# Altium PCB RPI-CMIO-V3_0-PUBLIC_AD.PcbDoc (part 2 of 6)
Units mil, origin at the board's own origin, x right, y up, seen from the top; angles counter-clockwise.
Board outline 3295.4 x 4105.44 mil, 6 copper layers (TOP, GNDT, PWRT, PWRB, GNDB, BOTTOM); 114 components, 152 nets, 703 pads, 476 vias.
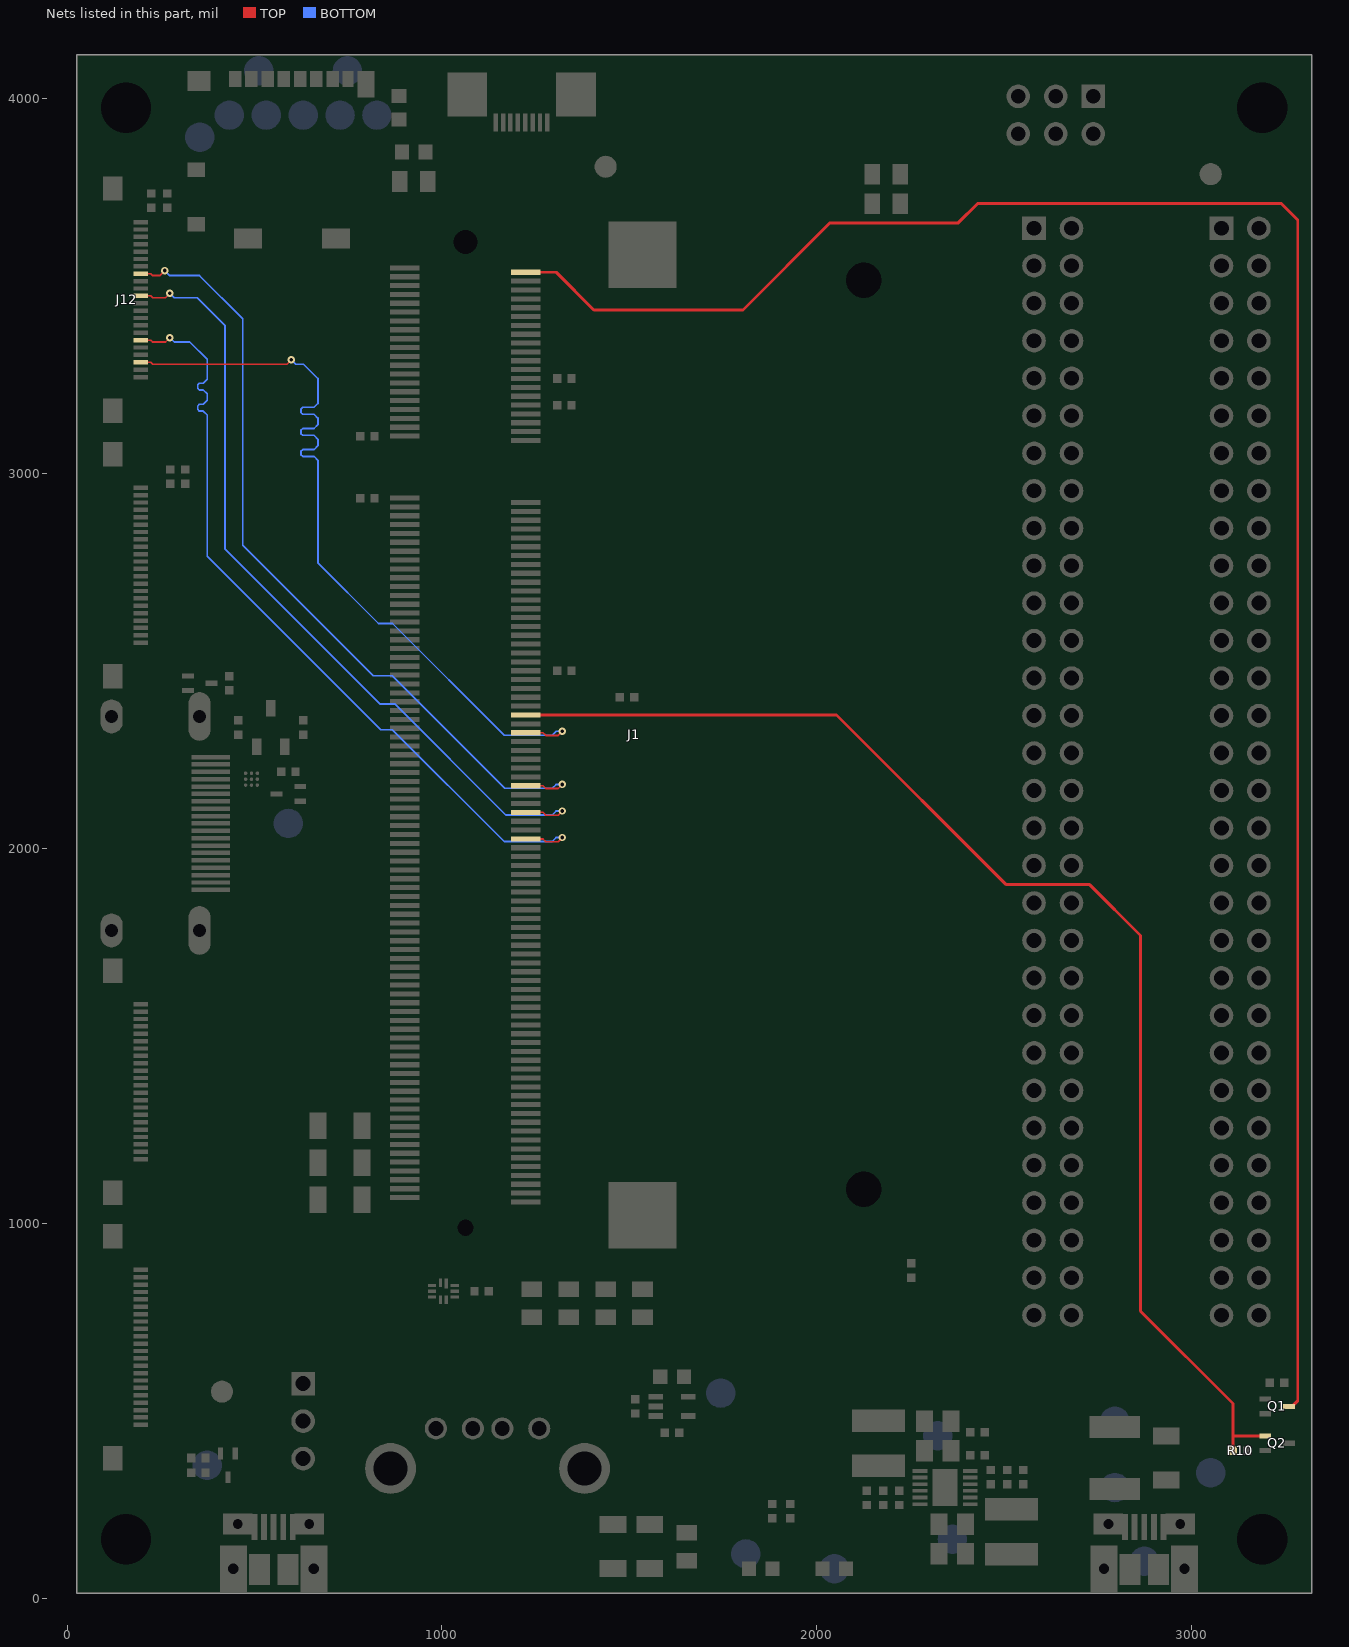
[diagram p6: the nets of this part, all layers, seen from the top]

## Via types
v1: diameter 19.68, hole 9.84, TOP to BOTTOM, 476 vias

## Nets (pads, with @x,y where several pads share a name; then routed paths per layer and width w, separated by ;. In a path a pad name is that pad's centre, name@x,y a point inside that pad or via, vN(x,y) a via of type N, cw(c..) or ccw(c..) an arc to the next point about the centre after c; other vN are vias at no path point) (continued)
DSI1_DP0: J1.94 J12.3 | length 2162.4
  TOP w4.53: J1.94@1224.41,2309.05 1269.72,2309.05 1277,2301.77 1310.25,2301.77 v1(1321.22,2312.74)
  TOP w4.57: J12.3@196.85,3297.24 223.39,3297.24 228.29,3292.34 586.81,3292.34 v1(598.42,3303.96)
  BOTTOM w4.57: v1(598.42,3303.96) 610.04,3292.35 631.08,3292.35 669.33,3254.09 669.33,3187.32 658.98,3176.96 628.62,3176.96 624.06,3172.39 624.06,3163.26 628.62,3158.69 658.98,3158.69 669.33,3148.34 669.33,3131.02 658.98,3120.66 628.62,3120.66 624.06,3116.09 624.06,3106.96 628.62,3102.39 658.98,3102.39 669.33,3092.04 669.33,3074.72 658.98,3064.36 628.62,3064.36 624.06,3059.8 624.06,3050.66 628.62,3046.1 658.98,3046.1 669.33,3035.74 669.33,2761.97 830.87,2600.43 868.27,2600.43 1166.52,2302.18 1294.23,2302.18 1304.79,2312.74 v1(1321.22,2312.74)
DSI1_DP1: J1.118 J12.6 | length 2171.9
  TOP w4.53: J1.118@1224.41,2025.59 1269.72,2025.59 1277,2018.31 1310.25,2018.31 v1(1321.22,2029.28)
  TOP w4.57: J12.6@196.85,3356.3 223.39,3356.3 228.29,3351.4 249,3351.4 262.7,3351.39 v1(274.32,3363.01)
  BOTTOM w4.57: v1(274.32,3363.01) 285.94,3351.39 327.74,3351.39 374.02,3305.12 374.02,3251.95 363.66,3241.6 353.03,3241.6 348.47,3237.03 348.47,3227.9 353.03,3223.33 363.66,3223.33 374.02,3212.98 374.02,3195.65 363.66,3185.3 353.03,3185.3 348.47,3180.73 348.47,3171.6 353.03,3167.03 363.66,3167.03 374.02,3156.68 374.02,2779.53 836.61,2316.93 868.11,2316.93 1166.32,2018.72 1294.23,2018.72 1304.79,2029.28 v1(1321.22,2029.28)
DSI1_DP2: J1.112 J12.12 | length 2165.8
  TOP w4.53: J1.112@1224.41,2096.46 1269.72,2096.46 1277,2089.17 1310.43,2089.17 v1(1321.26,2100)
  TOP w4.57: J12.12@196.85,3474.41 223.39,3474.41 228.29,3469.51 262.7,3469.51 v1(274.32,3481.13)
  BOTTOM w4.57: v1(274.32,3481.13) 285.93,3469.51 347.61,3469.51 421.3,3395.83 421.3,2799.37 834.8,2385.87 874.17,2385.87 1170.6,2089.44 1294.27,2089.44 1304.83,2100 v1(1321.26,2100)
DSI1_DP3: J1.106 J12.15 | length 2166.9
  TOP w4.53: J1.106@1224.41,2167.32 1269.72,2167.32 1277,2160.04 1310.25,2160.04 v1(1321.22,2171.01)
  TOP w4.57: J12.15@196.85,3533.46 223.39,3533.46 228.29,3528.56 247.04,3528.56 v1(260.38,3541.91)
  BOTTOM w4.57: v1(260.38,3541.91) 273.72,3528.56 353.33,3528.56 468.54,3413.35 468.54,2809.02 816.93,2460.63 868.11,2460.63 1168.29,2160.45 1294.23,2160.45 1304.79,2171.01 v1(1321.22,2171.01)
EMMC_DISABLE_N: J1.2 Q1.3 | length 5416.3
  TOP w7.87: J1.2@1224.41,3537.4 1305.12,3537.4 1405.51,3437.01 1803.15,3437.01 2035.43,3669.29 2377.95,3669.29 2429.13,3720.47 3240.16,3720.47 3283.46,3677.17 3283.46,526.58 3268.7,511.81 Q1.3@3259.84,511.81
EMMC_EN_N_1V8: J1.90 Q2.1 R10.2 | length 3445.8
  TOP w7.87: J1.90@1224.41,2356.3 2053.15,2356.3 2505.91,1903.54 2728.35,1903.54 2864.17,1767.72 2864.17,765.75 3110.83,519.1 3110.83,433.07 ; R10.2@3110.83,393.7 3110.83,433.07 ; Q2.1@3196.85,433.07 3110.83,433.07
